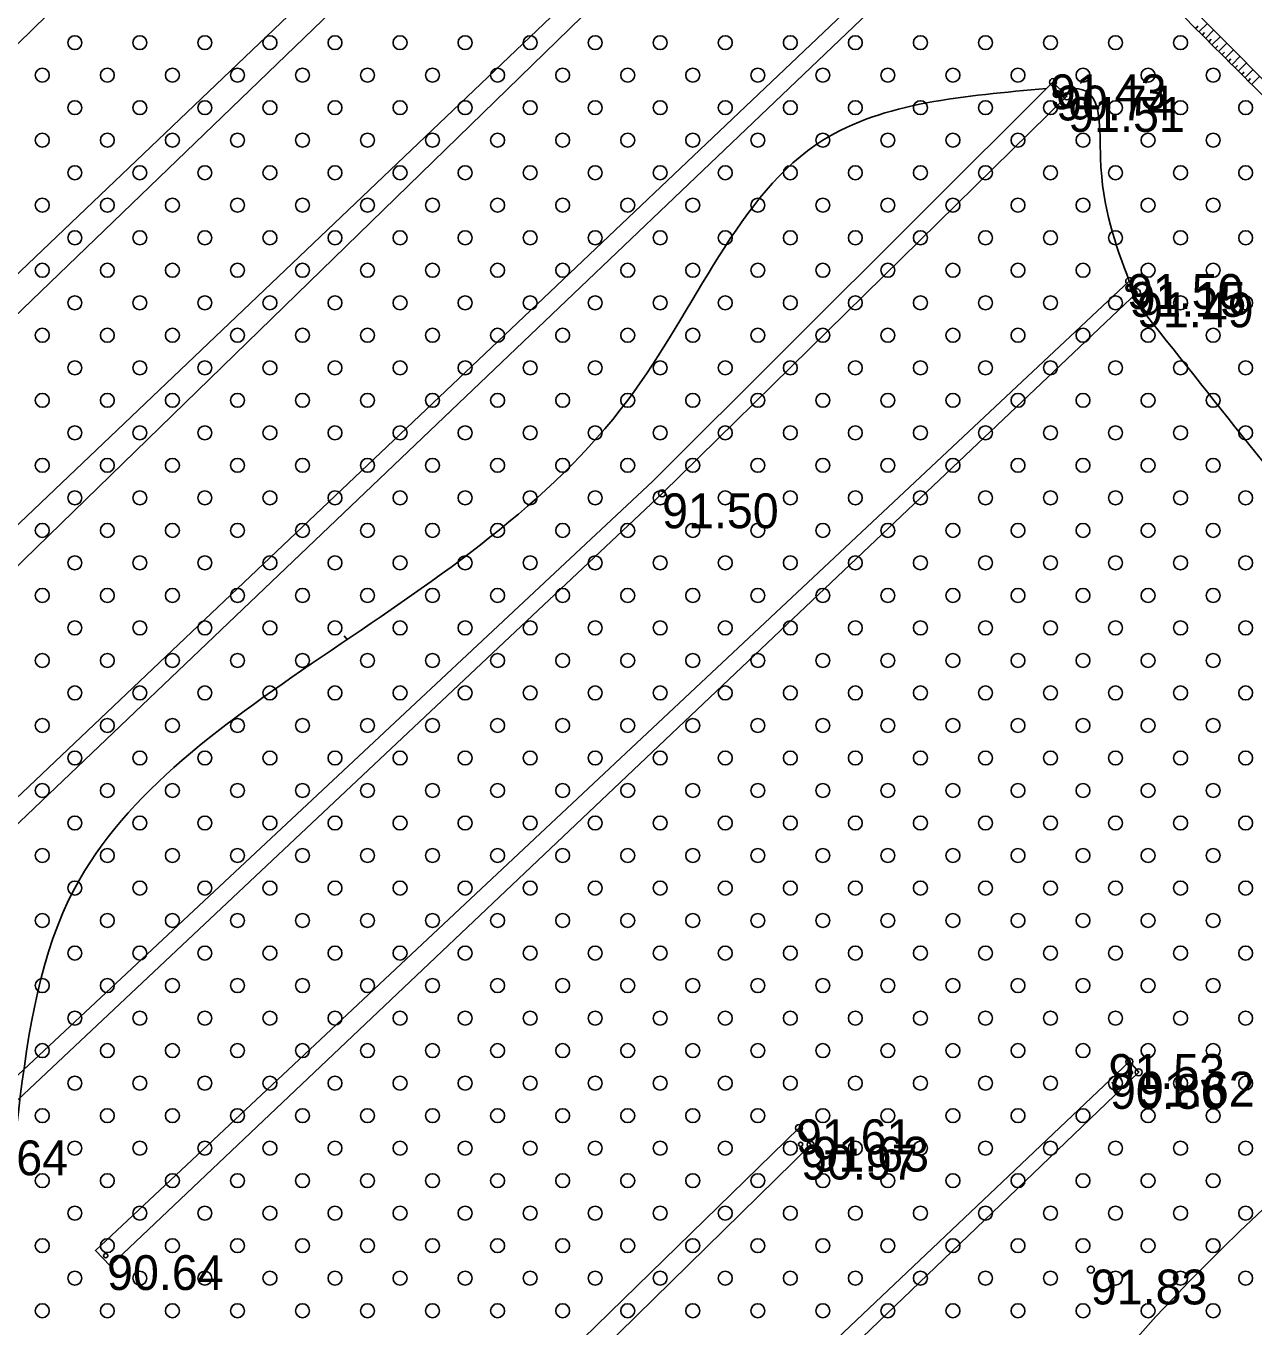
# Model space of a CAD drawing. Extents: x 316000 to 728450, y 314368 to 726000.
# Drawn here: x 725971.8 to 726103.9, y 315113.8 to 315253.8 of the extents above; entities that cross this region are included whole.
import ezdxf

# ---------------------------------------------------------------- set-up
doc = ezdxf.new("R2010")
doc.units = 0
for name, color, linetype in [('HIDG_ELEM_####_####_#', 7, 'Continuous'), ('HIDG_GRAV_####_####_#', 7, 'Continuous'), ('RELJ_AATZ_####_TKST_#', 7, 'Continuous'), ('RELJ_ELEM_####_####_#', 7, 'Continuous'), ('RELJ_HORZ_PAMT_####_#', 7, 'Continuous'), ('RELJ_NOGA_####_####_#', 7, 'Continuous'), ('TERT_ELEM_####_####_#', 7, 'Continuous'), ('TERT_KONT_####_####_#', 7, 'Continuous')]:
    doc.layers.add(name, color=color, linetype=linetype)

msp = doc.modelspace()

# ---------------------------------------------------------------- linework, layer by layer
at = {"layer": 'HIDG_ELEM_####_####_#'}
for centre in [(726082.67, 315246.47), (726090.49, 315225.6), (726090.6, 315141.14), (726055.11, 315133.41), (725980.33, 315121.43)]:
    msp.add_circle(centre, 0.225, dxfattribs=at)
at = {"layer": 'HIDG_GRAV_####_####_#'}
for points in [[(725741.16, 315628.11), (725806.06, 315558.99), (725870.9, 315491.87), (725934.12, 315427.08), (725995.78, 315361.63), (726059.85, 315293.4), (726126.03, 315226.73), (726194.49, 315154.86), (726259.18, 315086.52)], [(726026.72, 315310.03), (726028.38, 315308.12), (725929.27, 315211.22), (725849.42, 315136.82), (725847.67, 315137.8), (725927.82, 315213.86), (726026.72, 315310.03)], [(726041.22, 315294.28), (726042.74, 315292.12), (725933.2, 315186.57), (725862.99, 315121.84), (725861.5, 315123.44), (725931.43, 315189.54), (726041.22, 315294.28)], [(726054.58, 315279.91), (726055.6, 315278.2), (725943.43, 315169.03), (725940.91, 315171.62), (726054.58, 315279.91)], [(726067.39, 315262.47), (726068.58, 315261.15), (725954.8, 315152.62), (725890.85, 315090.51), (725889.28, 315091.99), (725953.78, 315154.65), (726067.39, 315262.47)], [(726082.26, 315247.75), (726083.77, 315246.23), (726040.2, 315203.48), (725905.19, 315076.43), (725903.68, 315078.01), (726039.2, 315204.79), (726082.26, 315247.75)], [(726090.47, 315226.34), (726091.31, 315225.1), (725980.79, 315120.33), (725979.21, 315122), (726090.47, 315226.34)], [(726040.8, 315092.53), (726091.49, 315141.17), (726090.49, 315142.31), (726039.19, 315093.71)], [(726054.94, 315135.17), (726056.2, 315133.35), (725999.87, 315078.06), (725998.18, 315079.78), (726054.94, 315135.17)]]:
    msp.add_lwpolyline(points, dxfattribs=at)
at = {"layer": 'RELJ_ELEM_####_####_#'}
for centre in [(726082.26, 315247.75), (726082.67, 315246.47), (726083.77, 315246.23), (726090.47, 315226.33), (726090.49, 315225.6), (726091.31, 315225.11), (726040.2, 315203.48), (726090.49, 315142.31), (726091.49, 315141.17), (726054.94, 315135.17), (726056.2, 315133.35), (726086.34, 315119.93)]:
    msp.add_circle(centre, 0.375, dxfattribs=at)
at = {"layer": 'RELJ_HORZ_PAMT_####_#'}
msp.add_line((726006, 315188.15), (726006.31, 315187.76), dxfattribs=at)
for points in [[(726116.34, 315699.09), (726105.94, 315702.69), (726040.13, 315715), (725990.82, 315710.42), (725942.03, 315708.25), (725920.28, 315706.77), (725880.37, 315714.51), (725859.05, 315708.68), (725859.05, 315672.66), (725851.26, 315613.97), (725853.47, 315568.9), (725841, 315555.79), (725885.56, 315509.63), (725935.94, 315461.49), (725983.42, 315406.25), (726032.86, 315360.51), (726082.85, 315311.19), (726122.23, 315248.76), (726137.05, 315229.29), (726180.19, 315183.1), (726194.52, 315168.27), (726211.91, 315146.93), (726212.51, 315143.16)], [(726081.57, 315247.05), (726057.5, 315241.5), (726036.5, 315213.5), (725977, 315161), (725966.5, 315108.5), (725903.5, 315045.5), (725862.12, 315076.6), (725805.5, 315130), (725759.7, 315178.88), (725709.89, 315228.8), (725646.99, 315287.19), (725634.68, 315314.96), (725629.04, 315327.48), (725557.35, 315340.26), (725478.3, 315344.16)], [(726090.47, 315226.34), (726087.38, 315239.6), (726085.55, 315246.9), (726083.02, 315246.99)], [(726208.53, 315137.52), (726189.05, 315133.53), (726141.5, 315164), (726090.79, 315224.6)]]:
    msp.add_spline(points, degree=3, dxfattribs=at)
at = {"layer": 'RELJ_NOGA_####_####_#'}
for p, q in [((726097.61, 315253.52), (726097.89, 315253.79)), ((726097.97, 315253.16), (726098.88, 315254.08)), ((726098.32, 315252.81), (726098.59, 315253.08)), ((726098.68, 315252.46), (726099.58, 315253.37)), ((726099.03, 315252.1), (726099.3, 315252.38)), ((726099.38, 315251.75), (726100.29, 315252.66)), ((726099.74, 315251.4), (726100.01, 315251.67)), ((726100.09, 315251.05), (726100.99, 315251.95)), ((726100.44, 315250.69), (726100.71, 315250.96)), ((726100.8, 315250.34), (726101.7, 315251.24)), ((726101.15, 315249.99), (726101.42, 315250.26)), ((726101.51, 315249.63), (726102.4, 315250.53)), ((726101.86, 315249.28), (726102.13, 315249.55)), ((726102.21, 315248.93), (726103.11, 315249.82)), ((726102.57, 315248.57), (726102.84, 315248.84)), ((726102.92, 315248.22), (726103.81, 315249.11)), ((726103.28, 315247.87), (726103.54, 315248.13)), ((726103.63, 315247.51), (726104.52, 315248.4))]:
    msp.add_line(p, q, dxfattribs=at)
for points in [[(726259.12, 315084.51), (726262.72, 315089.26), (726261.56, 315090.84), (726260.2, 315092.42), (726257.29, 315095.53), (726218.91, 315136.38), (726180.31, 315176.84), (726128.67, 315229.97), (726063.7, 315298.11), (725999.9, 315366.09), (725937.21, 315432.09), (725876.35, 315495.23), (725810.58, 315563.08), (725744.7, 315632.91)], [(725740.86, 315626.98), (725805.54, 315558.12), (725870.39, 315491.15), (725932.8, 315426.8), (725994.98, 315360.84), (726059.66, 315292.12), (726075.75, 315275.46), (726092.08, 315259.04), (726108.47, 315242.67), (726124.69, 315226.14), (726193.27, 315154.03), (726250.06, 315092.6), (726256.32, 315085.83), (726258.82, 315084.29), (726259.12, 315084.51)]]:
    msp.add_spline(points, degree=3, dxfattribs=at)
at = {"layer": 'TERT_ELEM_####_####_#'}
for centre in [(725977, 315252), (725984, 315252), (725991, 315252), (725998, 315252), (726005, 315252), (726012, 315252), (726019, 315252), (726026, 315252), (726033, 315252), (726040, 315252), (726047, 315252), (726054, 315252), (726061, 315252), (726068, 315252), (726075, 315252), (726082, 315252), (726089, 315252), (726096, 315252), (725973.5, 315248.5), (725980.5, 315248.5), (725987.5, 315248.5), (725994.5, 315248.5), (726001.5, 315248.5), (726008.5, 315248.5), (726015.5, 315248.5), (726022.5, 315248.5), (726029.5, 315248.5), (726036.5, 315248.5), (726043.5, 315248.5), (726050.5, 315248.5), (726057.5, 315248.5), (726064.5, 315248.5), (726071.5, 315248.5), (726078.5, 315248.5), (726085.5, 315248.5), (726092.5, 315248.5), (726099.5, 315248.5), (725977, 315245), (725984, 315245), (725991, 315245), (725998, 315245), (726005, 315245), (726012, 315245), (726019, 315245), (726026, 315245), (726033, 315245), (726040, 315245), (726047, 315245), (726054, 315245), (726061, 315245), (726068, 315245), (726075, 315245), (726082, 315245), (726089, 315245), (726096, 315245), (726103, 315245), (725973.5, 315241.5), (725980.5, 315241.5), (725987.5, 315241.5), (725994.5, 315241.5), (726001.5, 315241.5), (726008.5, 315241.5), (726015.5, 315241.5), (726022.5, 315241.5), (726029.5, 315241.5), (726036.5, 315241.5), (726043.5, 315241.5), (726050.5, 315241.5), (726057.5, 315241.5), (726064.5, 315241.5), (726071.5, 315241.5), (726078.5, 315241.5), (726085.5, 315241.5), (726092.5, 315241.5), (726099.5, 315241.5), (725977, 315238), (725984, 315238), (725991, 315238), (725998, 315238), (726005, 315238), (726012, 315238), (726019, 315238), (726026, 315238), (726033, 315238), (726040, 315238), (726047, 315238), (726054, 315238), (726061, 315238), (726068, 315238), (726075, 315238), (726082, 315238), (726089, 315238), (726096, 315238), (726103, 315238), (725973.5, 315234.5), (725980.5, 315234.5), (725987.5, 315234.5), (725994.5, 315234.5), (726001.5, 315234.5), (726008.5, 315234.5), (726015.5, 315234.5), (726022.5, 315234.5), (726029.5, 315234.5), (726036.5, 315234.5), (726043.5, 315234.5), (726050.5, 315234.5), (726057.5, 315234.5), (726064.5, 315234.5), (726071.5, 315234.5), (726078.5, 315234.5), (726085.5, 315234.5), (726092.5, 315234.5), (726099.5, 315234.5), (725977, 315231), (725984, 315231), (725991, 315231), (725998, 315231), (726005, 315231), (726012, 315231), (726019, 315231), (726026, 315231), (726033, 315231), (726040, 315231), (726047, 315231), (726054, 315231), (726061, 315231), (726068, 315231), (726075, 315231), (726082, 315231), (726089, 315231), (726096, 315231), (726103, 315231), (725973.5, 315227.5), (725980.5, 315227.5), (725987.5, 315227.5), (725994.5, 315227.5), (726001.5, 315227.5), (726008.5, 315227.5), (726015.5, 315227.5), (726022.5, 315227.5), (726029.5, 315227.5), (726036.5, 315227.5), (726043.5, 315227.5), (726050.5, 315227.5), (726057.5, 315227.5), (726064.5, 315227.5), (726071.5, 315227.5), (726078.5, 315227.5), (726085.5, 315227.5), (726092.5, 315227.5), (726099.5, 315227.5), (725977, 315224), (725984, 315224), (725991, 315224), (725998, 315224), (726005, 315224), (726012, 315224), (726019, 315224), (726026, 315224), (726033, 315224), (726040, 315224), (726047, 315224), (726054, 315224), (726061, 315224), (726068, 315224), (726075, 315224), (726082, 315224), (726089, 315224), (726096, 315224), (726103, 315224), (725973.5, 315220.5), (725980.5, 315220.5), (725987.5, 315220.5), (725994.5, 315220.5), (726001.5, 315220.5), (726008.5, 315220.5), (726015.5, 315220.5), (726022.5, 315220.5), (726029.5, 315220.5), (726036.5, 315220.5), (726043.5, 315220.5), (726050.5, 315220.5), (726057.5, 315220.5), (726064.5, 315220.5), (726071.5, 315220.5), (726078.5, 315220.5), (726085.5, 315220.5), (726092.5, 315220.5), (726099.5, 315220.5), (725977, 315217), (725984, 315217), (725991, 315217), (725998, 315217), (726005, 315217), (726012, 315217), (726019, 315217), (726026, 315217), (726033, 315217), (726040, 315217), (726047, 315217), (726054, 315217), (726061, 315217), (726068, 315217), (726075, 315217), (726082, 315217), (726089, 315217), (726096, 315217), (726103, 315217), (725973.5, 315213.5), (725980.5, 315213.5), (725987.5, 315213.5), (725994.5, 315213.5), (726001.5, 315213.5), (726008.5, 315213.5), (726015.5, 315213.5), (726022.5, 315213.5), (726029.5, 315213.5), (726036.5, 315213.5), (726043.5, 315213.5), (726050.5, 315213.5), (726057.5, 315213.5), (726064.5, 315213.5), (726071.5, 315213.5), (726078.5, 315213.5), (726085.5, 315213.5), (726092.5, 315213.5), (726099.5, 315213.5), (725977, 315210), (725984, 315210), (725991, 315210), (725998, 315210), (726005, 315210), (726012, 315210), (726019, 315210), (726026, 315210), (726033, 315210), (726040, 315210), (726047, 315210), (726054, 315210), (726061, 315210), (726068, 315210), (726075, 315210), (726082, 315210), (726089, 315210), (726096, 315210), (726103, 315210), (725973.5, 315206.5), (725980.5, 315206.5), (725987.5, 315206.5), (725994.5, 315206.5), (726001.5, 315206.5), (726008.5, 315206.5), (726015.5, 315206.5), (726022.5, 315206.5), (726029.5, 315206.5), (726036.5, 315206.5), (726043.5, 315206.5), (726050.5, 315206.5), (726057.5, 315206.5), (726064.5, 315206.5), (726071.5, 315206.5), (726078.5, 315206.5), (726085.5, 315206.5), (726092.5, 315206.5), (726099.5, 315206.5), (725977, 315203), (725984, 315203), (725991, 315203), (725998, 315203), (726005, 315203), (726012, 315203), (726019, 315203), (726026, 315203), (726033, 315203), (726040, 315203), (726047, 315203), (726054, 315203), (726061, 315203), (726068, 315203), (726075, 315203), (726082, 315203), (726089, 315203), (726096, 315203), (726103, 315203), (725973.5, 315199.5), (725980.5, 315199.5), (725987.5, 315199.5), (725994.5, 315199.5), (726001.5, 315199.5), (726008.5, 315199.5), (726015.5, 315199.5), (726022.5, 315199.5), (726029.5, 315199.5), (726036.5, 315199.5), (726043.5, 315199.5), (726050.5, 315199.5), (726057.5, 315199.5), (726064.5, 315199.5), (726071.5, 315199.5), (726078.5, 315199.5), (726085.5, 315199.5), (726092.5, 315199.5), (726099.5, 315199.5), (725977, 315196), (725984, 315196), (725991, 315196), (725998, 315196), (726005, 315196), (726012, 315196), (726019, 315196), (726026, 315196), (726033, 315196), (726040, 315196), (726047, 315196), (726054, 315196), (726061, 315196), (726068, 315196), (726075, 315196), (726082, 315196), (726089, 315196), (726096, 315196), (726103, 315196), (725973.5, 315192.5), (725980.5, 315192.5), (725987.5, 315192.5), (725994.5, 315192.5), (726001.5, 315192.5), (726008.5, 315192.5), (726015.5, 315192.5), (726022.5, 315192.5), (726029.5, 315192.5), (726036.5, 315192.5), (726043.5, 315192.5), (726050.5, 315192.5), (726057.5, 315192.5), (726064.5, 315192.5), (726071.5, 315192.5), (726078.5, 315192.5), (726085.5, 315192.5), (726092.5, 315192.5), (726099.5, 315192.5), (725977, 315189), (725984, 315189), (725991, 315189), (725998, 315189), (726005, 315189), (726012, 315189), (726019, 315189), (726026, 315189), (726033, 315189), (726040, 315189), (726047, 315189), (726054, 315189), (726061, 315189), (726068, 315189), (726075, 315189), (726082, 315189), (726089, 315189), (726096, 315189), (726103, 315189), (725973.5, 315185.5), (725980.5, 315185.5), (725987.5, 315185.5), (725994.5, 315185.5), (726001.5, 315185.5), (726008.5, 315185.5), (726015.5, 315185.5), (726022.5, 315185.5), (726029.5, 315185.5), (726036.5, 315185.5), (726043.5, 315185.5), (726050.5, 315185.5), (726057.5, 315185.5), (726064.5, 315185.5), (726071.5, 315185.5), (726078.5, 315185.5), (726085.5, 315185.5), (726092.5, 315185.5), (726099.5, 315185.5), (725977, 315182), (725984, 315182), (725991, 315182), (725998, 315182), (726005, 315182), (726012, 315182), (726019, 315182), (726026, 315182), (726033, 315182), (726040, 315182), (726047, 315182), (726054, 315182), (726061, 315182), (726068, 315182), (726075, 315182), (726082, 315182), (726089, 315182), (726096, 315182), (726103, 315182), (725973.5, 315178.5), (725980.5, 315178.5), (725987.5, 315178.5), (725994.5, 315178.5), (726001.5, 315178.5), (726008.5, 315178.5), (726015.5, 315178.5), (726022.5, 315178.5), (726029.5, 315178.5), (726036.5, 315178.5), (726043.5, 315178.5), (726050.5, 315178.5), (726057.5, 315178.5), (726064.5, 315178.5), (726071.5, 315178.5), (726078.5, 315178.5), (726085.5, 315178.5), (726092.5, 315178.5), (726099.5, 315178.5), (725977, 315175), (725984, 315175), (725991, 315175), (725998, 315175), (726005, 315175), (726012, 315175), (726019, 315175), (726026, 315175), (726033, 315175), (726040, 315175), (726047, 315175), (726054, 315175), (726061, 315175), (726068, 315175), (726075, 315175), (726082, 315175), (726089, 315175), (726096, 315175), (726103, 315175), (725973.5, 315171.5), (725980.5, 315171.5), (725987.5, 315171.5), (725994.5, 315171.5), (726001.5, 315171.5), (726008.5, 315171.5), (726015.5, 315171.5), (726022.5, 315171.5), (726029.5, 315171.5), (726036.5, 315171.5), (726043.5, 315171.5), (726050.5, 315171.5), (726057.5, 315171.5), (726064.5, 315171.5), (726071.5, 315171.5), (726078.5, 315171.5), (726085.5, 315171.5), (726092.5, 315171.5), (726099.5, 315171.5), (725977, 315168), (725984, 315168), (725991, 315168), (725998, 315168), (726005, 315168), (726012, 315168), (726019, 315168), (726026, 315168), (726033, 315168), (726040, 315168), (726047, 315168), (726054, 315168), (726061, 315168), (726068, 315168), (726075, 315168), (726082, 315168), (726089, 315168), (726096, 315168), (726103, 315168), (725973.5, 315164.5), (725980.5, 315164.5), (725987.5, 315164.5), (725994.5, 315164.5), (726001.5, 315164.5), (726008.5, 315164.5), (726015.5, 315164.5), (726022.5, 315164.5), (726029.5, 315164.5), (726036.5, 315164.5), (726043.5, 315164.5), (726050.5, 315164.5), (726057.5, 315164.5), (726064.5, 315164.5), (726071.5, 315164.5), (726078.5, 315164.5), (726085.5, 315164.5), (726092.5, 315164.5), (726099.5, 315164.5), (725977, 315161), (725984, 315161), (725991, 315161), (725998, 315161), (726005, 315161), (726012, 315161), (726019, 315161), (726026, 315161), (726033, 315161), (726040, 315161), (726047, 315161), (726054, 315161), (726061, 315161), (726068, 315161), (726075, 315161), (726082, 315161), (726089, 315161), (726096, 315161), (726103, 315161), (725973.5, 315157.5), (725980.5, 315157.5), (725987.5, 315157.5), (725994.5, 315157.5), (726001.5, 315157.5), (726008.5, 315157.5), (726015.5, 315157.5), (726022.5, 315157.5), (726029.5, 315157.5), (726036.5, 315157.5), (726043.5, 315157.5), (726050.5, 315157.5), (726057.5, 315157.5), (726064.5, 315157.5), (726071.5, 315157.5), (726078.5, 315157.5), (726085.5, 315157.5), (726092.5, 315157.5), (726099.5, 315157.5), (725977, 315154), (725984, 315154), (725991, 315154), (725998, 315154), (726005, 315154), (726012, 315154), (726019, 315154), (726026, 315154), (726033, 315154), (726040, 315154), (726047, 315154), (726054, 315154), (726061, 315154), (726068, 315154), (726075, 315154), (726082, 315154), (726089, 315154), (726096, 315154), (726103, 315154), (725973.5, 315150.5), (725980.5, 315150.5), (725987.5, 315150.5), (725994.5, 315150.5), (726001.5, 315150.5), (726008.5, 315150.5), (726015.5, 315150.5), (726022.5, 315150.5), (726029.5, 315150.5), (726036.5, 315150.5), (726043.5, 315150.5), (726050.5, 315150.5), (726057.5, 315150.5), (726064.5, 315150.5), (726071.5, 315150.5), (726078.5, 315150.5), (726085.5, 315150.5), (726092.5, 315150.5), (726099.5, 315150.5), (725977, 315147), (725984, 315147), (725991, 315147), (725998, 315147), (726005, 315147), (726012, 315147), (726019, 315147), (726026, 315147), (726033, 315147), (726040, 315147), (726047, 315147), (726054, 315147), (726061, 315147), (726068, 315147), (726075, 315147), (726082, 315147), (726089, 315147), (726096, 315147), (726103, 315147), (725973.5, 315143.5), (725980.5, 315143.5), (725987.5, 315143.5), (725994.5, 315143.5), (726001.5, 315143.5), (726008.5, 315143.5), (726015.5, 315143.5), (726022.5, 315143.5), (726029.5, 315143.5), (726036.5, 315143.5), (726043.5, 315143.5), (726050.5, 315143.5), (726057.5, 315143.5), (726064.5, 315143.5), (726071.5, 315143.5), (726078.5, 315143.5), (726085.5, 315143.5), (726092.5, 315143.5), (726099.5, 315143.5), (725977, 315140), (725984, 315140), (725991, 315140), (725998, 315140), (726005, 315140), (726012, 315140), (726019, 315140), (726026, 315140), (726033, 315140), (726040, 315140), (726047, 315140), (726054, 315140), (726061, 315140), (726068, 315140), (726075, 315140), (726082, 315140), (726089, 315140), (726096, 315140), (726103, 315140), (725973.5, 315136.5), (725980.5, 315136.5), (725987.5, 315136.5), (725994.5, 315136.5), (726001.5, 315136.5), (726008.5, 315136.5), (726015.5, 315136.5), (726022.5, 315136.5), (726029.5, 315136.5), (726036.5, 315136.5), (726043.5, 315136.5), (726050.5, 315136.5), (726057.5, 315136.5), (726064.5, 315136.5), (726071.5, 315136.5), (726078.5, 315136.5), (726085.5, 315136.5), (726092.5, 315136.5), (726099.5, 315136.5), (725977, 315133), (725984, 315133), (725991, 315133), (725998, 315133), (726005, 315133), (726012, 315133), (726019, 315133), (726026, 315133), (726033, 315133), (726040, 315133), (726047, 315133), (726054, 315133), (726061, 315133), (726068, 315133), (726075, 315133), (726082, 315133), (726089, 315133), (726096, 315133), (726103, 315133), (725973.5, 315129.5), (725980.5, 315129.5), (725987.5, 315129.5), (725994.5, 315129.5), (726001.5, 315129.5), (726008.5, 315129.5), (726015.5, 315129.5), (726022.5, 315129.5), (726029.5, 315129.5), (726036.5, 315129.5), (726043.5, 315129.5), (726050.5, 315129.5), (726057.5, 315129.5), (726064.5, 315129.5), (726071.5, 315129.5), (726078.5, 315129.5), (726085.5, 315129.5), (726092.5, 315129.5), (726099.5, 315129.5), (725977, 315126), (725984, 315126), (725991, 315126), (725998, 315126), (726005, 315126), (726012, 315126), (726019, 315126), (726026, 315126), (726033, 315126), (726040, 315126), (726047, 315126), (726054, 315126), (726061, 315126), (726068, 315126), (726075, 315126), (726082, 315126), (726089, 315126), (726096, 315126), (726103, 315126), (725973.5, 315122.5), (725980.5, 315122.5), (725987.5, 315122.5), (725994.5, 315122.5), (726001.5, 315122.5), (726008.5, 315122.5), (726015.5, 315122.5), (726022.5, 315122.5), (726029.5, 315122.5), (726036.5, 315122.5), (726043.5, 315122.5), (726050.5, 315122.5), (726057.5, 315122.5), (726064.5, 315122.5), (726071.5, 315122.5), (726078.5, 315122.5), (726085.5, 315122.5), (726092.5, 315122.5), (726099.5, 315122.5), (725977, 315119), (725984, 315119), (725991, 315119), (725998, 315119), (726005, 315119), (726012, 315119), (726019, 315119), (726026, 315119), (726033, 315119), (726040, 315119), (726047, 315119), (726054, 315119), (726061, 315119), (726068, 315119), (726075, 315119), (726082, 315119), (726089, 315119), (726096, 315119), (726103, 315119), (725973.5, 315115.5), (725980.5, 315115.5), (725987.5, 315115.5), (725994.5, 315115.5), (726001.5, 315115.5), (726008.5, 315115.5), (726015.5, 315115.5), (726022.5, 315115.5), (726029.5, 315115.5), (726036.5, 315115.5), (726043.5, 315115.5), (726050.5, 315115.5), (726057.5, 315115.5), (726064.5, 315115.5), (726071.5, 315115.5), (726078.5, 315115.5), (726085.5, 315115.5), (726092.5, 315115.5), (726099.5, 315115.5)]:
    msp.add_circle(centre, 0.75, dxfattribs=at)
at = {"layer": 'TERT_KONT_####_####_#'}
msp.add_spline([(726171.05, 315177.78), (726060.22, 315058.34), (726046.85, 314926.57), (725966, 314840.49), (725918.95, 314808.85), (725841.04, 314808.85), (725695.46, 314898.17)], degree=3, dxfattribs=at)

# ---------------------------------------------------------------- texts
at = {"layer": 'RELJ_AATZ_####_TKST_#'}
for s, p in [('91.43', (726081.93, 315244.83)), ('90.74', (726082.6, 315243.63)), ('91.51', (726083.91, 315242.4)), ('91.50', (726090.23, 315223.34)), ('91.15', (726090.51, 315222.49)), ('91.49', (726091.31, 315221.36)), ('91.50', (726040.2, 315199.73)), ('91.53', (726088.24, 315139.38)), ('90.86', (726088.4, 315137.23)), ('91.62', (726091.42, 315137.48)), ('91.61', (726054.61, 315132.35)), ('91.63', (726056.38, 315130.48)), ('90.64', (725963.73, 315130.08)), ('90.97', (726055.15, 315129.62)), ('90.64', (725980.47, 315117.73)), ('91.83', (726086.34, 315116.18))]:
    msp.add_text(s, height=3.75, dxfattribs=at).set_placement(p)

doc.saveas('drawing.dxf')
